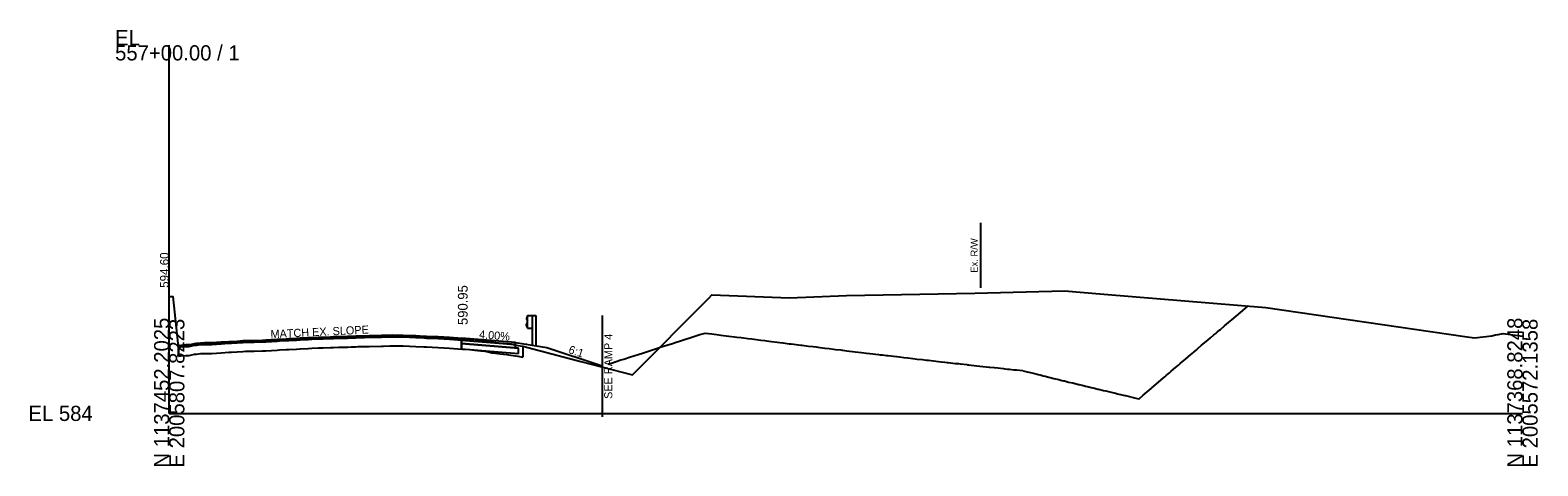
# Model space of a CAD drawing. Extents: x -201 to 2007062, y -213 to 1139737.
# Drawn here: x -25.7 to 252.8, y 9490.3 to 9570.8 of the extents above; entities that cross this region are included whole.
import ezdxf

# ---------------------------------------------------------------- set-up
doc = ezdxf.new("R2010")
doc.units = 0
for name, color, linetype in [('Default', 7, 'Continuous'), ('RD_DTM_Design_FG', 7, 'Continuous'), ('RD_GPK_XS_Cell', 7, 'Continuous'), ('RD_Sketch1', 7, 'Continuous'), ('RD_XS_Base', 7, 'Continuous'), ('RD_XS_ExGround', 7, 'Continuous'), ('RD_XS_ExPaveRet', 7, 'Continuous'), ('RD_XS_ExRW', 7, 'Continuous'), ('RD_XS_GR', 7, 'Continuous'), ('RD_XS_PaveOvlay', 7, 'Continuous'), ('RD_XS_PaveShd', 7, 'Continuous'), ('RD_XS_SideStreet', 7, 'Continuous'), ('RD_XS_TieSlope', 7, 'Continuous'), ('RD_XS_TX_Elev_EX', 7, 'Continuous'), ('RD_XS_TX_Elev_PR', 7, 'Continuous'), ('RD_XS_TX_Slope', 7, 'Continuous')]:
    doc.layers.add(name, color=color, linetype=linetype)

msp = doc.modelspace()

# ---------------------------------------------------------------- linework, layer by layer
at = {"layer": 'RD_DTM_Design_FG'}
msp.add_lwpolyline([(81, 9509.09), (81.13, 9509.13), (81.62, 9509.29), (81.7, 9509.31), (83.45, 9509.87), (83.96, 9510.04), (85.01, 9510.37), (86.64, 9510.9), (87.64, 9511.22), (88.57, 9511.52), (89.86, 9511.93), (90.22, 9512.05), (90.23, 9512.05), (90.91, 9512.27), (92.95, 9512.92), (93.84, 9513.2), (94.09, 9513.28), (94.64, 9513.46), (95.21, 9513.64), (96.15, 9513.95), (98.05, 9514.55), (98.99, 9514.85), (100.26, 9514.69), (100.7, 9514.63), (101.14, 9514.58), (101.54, 9514.52), (101.91, 9514.48), (103.39, 9514.29), (104.4, 9514.16), (104.83, 9514.11), (105.66, 9514), (106.08, 9513.95), (106.88, 9513.85), (107.61, 9513.75), (109.28, 9513.54), (110.02, 9513.45), (110.77, 9513.35), (112.79, 9513.1), (113.34, 9513.03), (113.41, 9513.02), (114.52, 9512.88), (114.87, 9512.84), (115.39, 9512.78), (116.67, 9512.62), (116.92, 9512.59), (118.08, 9512.44), (118.98, 9512.33), (119.49, 9512.27), (119.82, 9512.23), (121.11, 9512.07), (121.94, 9511.97), (122.69, 9511.88), (123.08, 9511.83), (124.06, 9511.72), (124.32, 9511.68), (124.47, 9511.67), (125.18, 9511.58), (126.74, 9511.39), (127.9, 9511.25), (128.82, 9511.14), (129.46, 9511.07), (131.02, 9510.88), (131.32, 9510.85), (131.75, 9510.8), (132.49, 9510.71), (132.83, 9510.67), (133.8, 9510.56), (134.39, 9510.49), (134.89, 9510.43), (135.72, 9510.33), (136.47, 9510.25), (137.35, 9510.14), (138.17, 9510.05), (139.15, 9509.94), (139.92, 9509.85), (140.04, 9509.84), (140.28, 9509.81), (142.09, 9509.6), (142.63, 9509.54), (143.29, 9509.47), (143.73, 9509.42), (143.93, 9509.4), (145.21, 9509.25), (145.8, 9509.19), (146.11, 9509.15), (147.39, 9509.01), (147.48, 9509), (147.5, 9509), (147.73, 9508.97), (148.14, 9508.93), (148.18, 9508.92), (149.78, 9508.75), (151.5, 9508.56), (151.6, 9508.55), (152.4, 9508.46), (152.45, 9508.46), (153.05, 9508.39), (154.15, 9508.28), (154.34, 9508.26), (154.88, 9508.2), (155.22, 9508.16), (156.05, 9508.07), (156.52, 9508.02), (157.72, 9507.9), (157.76, 9507.89), (158.47, 9507.71), (159.14, 9507.54), (160.08, 9507.31), (160.36, 9507.23), (160.5, 9507.2), (160.92, 9507.1), (161.46, 9506.96), (161.82, 9506.87), (163.43, 9506.47), (164.35, 9506.24), (164.93, 9506.1), (165.21, 9506.03), (165.37, 9505.99), (166.16, 9505.8), (166.91, 9505.62), (167.98, 9505.35), (168.08, 9505.33), (168.67, 9505.19), (169.27, 9505.04), (169.91, 9504.88), (170.34, 9504.78), (170.92, 9504.64), (171.15, 9504.59), (171.57, 9504.48), (171.7, 9504.45), (172.59, 9504.24), (173.02, 9504.14), (173.78, 9503.96), (173.99, 9503.91), (174.8, 9503.72), (175.2, 9503.62), (176.51, 9503.31), (176.56, 9503.3), (176.64, 9503.28), (178.6, 9502.82), (179.15, 9502.7), (179.18, 9502.69), (179.95, 9503.36), (181.4, 9504.6), (181.59, 9504.76), (181.81, 9504.96), (181.9, 9505.03), (183.67, 9506.55), (183.9, 9506.75), (184.19, 9507), (184.79, 9507.52), (185.11, 9507.79), (185.88, 9508.45), (186.17, 9508.69), (186.43, 9508.92), (186.77, 9509.21), (187.42, 9509.76), (187.74, 9510.03), (188.22, 9510.45), (188.76, 9510.9), (188.89, 9511.02), (189.32, 9511.39), (189.7, 9511.71), (190.09, 9512.04), (190.72, 9512.58), (191.25, 9513.03), (191.92, 9513.6), (192.37, 9513.97), (192.39, 9513.99), (193, 9514.51), (193.32, 9514.77), (193.58, 9515), (194.08, 9515.41), (194.2, 9515.53), (194.96, 9516.16), (195.68, 9516.77), (196.29, 9517.28), (197.08, 9517.94), (197.48, 9518.28), (197.6, 9518.39), (197.84, 9518.58), (199.35, 9519.85)], dxfattribs=at)
at = {"layer": 'RD_GPK_XS_Cell'}
for q in [(0, 9568.02), (250, 9500)]:
    msp.add_line((0, 9500), q, dxfattribs=at)
at = {"layer": 'RD_XS_Base'}
for points in [[(64, 9512.76), (54, 9513.56)], [(54, 9513.56), (54, 9512.9)], [(64.5, 9512.06), (54, 9512.9)], [(54, 9512.9), (54, 9511.9)], [(54, 9512.9), (64.5, 9512.06)], [(54, 9511.9), (64.5, 9511.06)], [(64, 9512.1), (64, 9512.76)], [(64.5, 9511.06), (64.5, 9512.06)]]:
    msp.add_lwpolyline(points, dxfattribs=at)
at = {"layer": 'RD_XS_ExGround'}
msp.add_lwpolyline([(0, 9521.2), (0.04, 9521.6), (0.65, 9521.63), (1.6, 9512.92), (1.72, 9512.56), (2.16, 9512.61), (3.09, 9512.7), (3.69, 9512.71), (4.16, 9512.81), (4.68, 9512.92), (5.04, 9512.97), (5.79, 9513.04), (6.5, 9513.07), (6.88, 9513.07), (7.85, 9513.09), (9.6, 9513.21), (10.99, 9513.29), (11.48, 9513.31), (12.56, 9513.36), (13.6, 9513.44), (14.12, 9513.47), (15.72, 9513.5), (17.26, 9513.55), (17.84, 9513.59), (18.9, 9513.64), (19.97, 9513.71), (20.39, 9513.72), (21.6, 9513.79), (22.09, 9513.82), (23.53, 9513.89), (24.21, 9513.94), (25.64, 9514.01), (26.33, 9514.04), (27.59, 9514.09), (28.45, 9514.11), (29.79, 9514.17), (30.36, 9514.19), (31.25, 9514.23), (32.93, 9514.25), (33.59, 9514.28), (34.5, 9514.32), (34.82, 9514.33), (36.06, 9514.36), (36.94, 9514.39), (39.2, 9514.45), (39.59, 9514.45), (40.76, 9514.48), (41.18, 9514.49), (43.24, 9514.46), (45.58, 9514.37), (47.03, 9514.3), (47.54, 9514.27), (48.6, 9514.23), (49.67, 9514.18), (51.79, 9514.06), (53.3, 9513.94), (54.19, 9513.88), (55.56, 9513.78), (56.43, 9513.7), (57.58, 9513.59), (58.28, 9513.49), (59.17, 9513.31), (59.57, 9513.22), (60.27, 9513.1), (61.14, 9513), (62.39, 9512.88), (62.7, 9512.84), (63.57, 9512.7), (64.43, 9512.57), (65.34, 9512.4), (76.05, 9509.58), (85.58, 9507.1), (99.72, 9521.36), (100.27, 9521.91), (114.57, 9521.38), (125.11, 9521.77), (148.84, 9522.19), (165.42, 9522.67), (172.63, 9522.06), (202.57, 9519.59), (239.36, 9514.21), (241.13, 9513.95), (244.33, 9514.36), (245.02, 9514.49), (245.53, 9514.59), (246.45, 9514.77), (249.13, 9514.38), (250, 9514.25)], dxfattribs=at)
at = {"layer": 'RD_XS_ExPaveRet'}
for p, q in [((1.72, 9510.56), (1.72, 9512.56)), ((1.72, 9512.23), (1.72, 9510.56)), ((22.09, 9511.82), (23.53, 9511.89)), ((22.09, 9511.82), (23.53, 9511.89)), ((23.53, 9511.89), (24.21, 9511.94)), ((23.53, 9511.89), (24.21, 9511.94)), ((24.21, 9511.94), (25.64, 9512.01)), ((24.21, 9511.94), (25.64, 9512.01)), ((25.64, 9512.01), (26.33, 9512.04)), ((25.64, 9512.01), (26.33, 9512.04)), ((26.33, 9512.04), (27.59, 9512.09)), ((26.33, 9512.04), (27.59, 9512.09)), ((27.59, 9512.09), (28.45, 9512.11)), ((27.59, 9512.09), (28.45, 9512.11)), ((28.45, 9512.11), (29.79, 9512.17)), ((28.45, 9512.11), (29.79, 9512.17)), ((29.79, 9512.17), (30.36, 9512.19)), ((29.79, 9512.17), (30.36, 9512.19)), ((30.36, 9512.19), (31.25, 9512.23)), ((30.36, 9512.19), (31.25, 9512.23)), ((31.25, 9512.23), (32.93, 9512.25)), ((31.25, 9512.23), (32.93, 9512.25)), ((32.93, 9512.25), (33.59, 9512.28)), ((32.93, 9512.25), (33.59, 9512.28)), ((33.59, 9512.28), (34.5, 9512.32)), ((33.59, 9512.28), (34.5, 9512.32)), ((34.5, 9512.32), (34.82, 9512.33)), ((34.5, 9512.32), (34.82, 9512.33)), ((34.82, 9512.33), (36.06, 9512.36)), ((34.82, 9512.33), (36.06, 9512.36)), ((36.06, 9512.36), (36.94, 9512.39)), ((36.06, 9512.36), (36.94, 9512.39)), ((36.94, 9512.39), (39.2, 9512.45)), ((36.94, 9512.39), (39.2, 9512.45)), ((39.2, 9512.45), (39.59, 9512.45)), ((39.2, 9512.45), (39.59, 9512.45)), ((39.59, 9512.45), (40.76, 9512.48)), ((39.59, 9512.45), (40.76, 9512.48)), ((40.76, 9512.48), (41.18, 9512.49)), ((40.76, 9512.48), (41.18, 9512.49)), ((41.18, 9512.49), (43.24, 9512.46)), ((41.18, 9512.49), (43.24, 9512.46)), ((43.24, 9512.46), (45.58, 9512.37)), ((43.24, 9512.46), (45.58, 9512.37)), ((45.58, 9512.37), (47.03, 9512.3)), ((45.58, 9512.37), (47.03, 9512.3)), ((47.03, 9512.3), (47.54, 9512.27)), ((47.03, 9512.3), (47.54, 9512.27)), ((47.54, 9512.27), (48.6, 9512.23)), ((47.54, 9512.27), (48.6, 9512.23)), ((48.6, 9512.23), (49.67, 9512.18)), ((48.6, 9512.23), (49.67, 9512.18)), ((49.67, 9512.18), (51.79, 9512.06)), ((49.67, 9512.18), (51.79, 9512.06)), ((51.79, 9512.06), (53.3, 9511.94)), ((51.79, 9512.06), (53.3, 9511.94)), ((53.3, 9511.94), (54.19, 9511.88)), ((53.3, 9511.94), (54, 9511.89)), ((54, 9512.9), (54, 9513.56)), ((54, 9511.9), (54, 9512.9)), ((54, 9511.9), (54, 9511.89)), ((54, 9511.89), (54, 9511.9)), ((65.34, 9512.4), (65.34, 9510.4)), ((1.72, 9510.56), (2.16, 9510.61)), ((1.72, 9510.56), (2.16, 9510.61)), ((2.16, 9510.61), (3.09, 9510.7)), ((2.16, 9510.61), (3.09, 9510.7)), ((3.09, 9510.7), (3.69, 9510.71)), ((3.09, 9510.7), (3.69, 9510.71)), ((3.69, 9510.71), (4.16, 9510.81)), ((3.69, 9510.71), (4.16, 9510.81)), ((4.16, 9510.81), (4.68, 9510.92)), ((4.16, 9510.81), (4.68, 9510.92)), ((4.68, 9510.92), (5.04, 9510.97)), ((4.68, 9510.92), (5.04, 9510.97)), ((5.04, 9510.97), (5.79, 9511.04)), ((5.04, 9510.97), (5.79, 9511.04)), ((5.79, 9511.04), (6.5, 9511.07)), ((5.79, 9511.04), (6.5, 9511.07)), ((6.5, 9511.07), (6.88, 9511.07)), ((6.5, 9511.07), (6.88, 9511.07)), ((6.88, 9511.07), (7.85, 9511.09)), ((6.88, 9511.07), (7.85, 9511.09)), ((7.85, 9511.09), (9.6, 9511.21)), ((7.85, 9511.09), (9.6, 9511.21)), ((9.6, 9511.21), (10.99, 9511.29)), ((9.6, 9511.21), (10.99, 9511.29)), ((10.99, 9511.29), (11.48, 9511.31)), ((10.99, 9511.29), (11.48, 9511.31)), ((11.48, 9511.31), (12.56, 9511.36)), ((11.48, 9511.31), (12.56, 9511.36)), ((12.56, 9511.36), (13.6, 9511.44)), ((12.56, 9511.36), (13.6, 9511.44)), ((13.6, 9511.44), (14.12, 9511.47)), ((13.6, 9511.44), (14.12, 9511.47)), ((14.12, 9511.47), (15.72, 9511.5)), ((14.12, 9511.47), (15.72, 9511.5)), ((15.72, 9511.5), (17.26, 9511.55)), ((15.72, 9511.5), (17.26, 9511.55)), ((17.26, 9511.55), (17.84, 9511.59)), ((17.26, 9511.55), (17.84, 9511.59)), ((17.84, 9511.59), (18.9, 9511.64)), ((17.84, 9511.59), (18.9, 9511.64)), ((18.9, 9511.64), (19.97, 9511.71)), ((18.9, 9511.64), (19.97, 9511.71)), ((19.97, 9511.71), (20.39, 9511.72)), ((19.97, 9511.71), (20.39, 9511.72)), ((20.39, 9511.72), (21.6, 9511.79)), ((20.39, 9511.72), (21.6, 9511.79)), ((21.6, 9511.79), (22.09, 9511.82)), ((21.6, 9511.79), (22.09, 9511.82)), ((54.19, 9511.88), (55.56, 9511.78)), ((55.56, 9511.78), (56.43, 9511.7)), ((56.43, 9511.7), (57.58, 9511.59)), ((57.58, 9511.59), (58.28, 9511.49)), ((58.28, 9511.49), (59.17, 9511.31)), ((59.17, 9511.31), (59.57, 9511.22)), ((59.57, 9511.22), (60.27, 9511.1)), ((60.27, 9511.1), (61.14, 9511)), ((61.14, 9511), (62.39, 9510.88)), ((62.39, 9510.88), (62.7, 9510.84)), ((62.7, 9510.84), (63.57, 9510.7)), ((63.57, 9510.7), (64.43, 9510.57)), ((64.43, 9510.57), (65.34, 9510.4))]:
    msp.add_line(p, q, dxfattribs=at)
for points in [[(54, 9513.56), (53.3, 9513.61), (51.79, 9513.72), (49.67, 9513.85), (48.6, 9513.9), (47.54, 9513.93), (47.03, 9513.96), (45.58, 9514.04), (43.24, 9514.13), (41.18, 9514.16), (40.76, 9514.15), (39.59, 9514.12), (39.2, 9514.11), (36.94, 9514.06), (36.06, 9514.03), (34.82, 9514), (34.5, 9513.99), (33.59, 9513.95), (32.93, 9513.92), (31.25, 9513.9), (30.36, 9513.86), (29.79, 9513.84), (28.45, 9513.78), (27.59, 9513.75), (26.33, 9513.71), (25.64, 9513.67), (24.21, 9513.61), (23.53, 9513.56), (22.09, 9513.49), (21.6, 9513.46), (20.39, 9513.39), (19.97, 9513.37), (18.9, 9513.31), (17.84, 9513.25), (17.26, 9513.22), (15.72, 9513.17), (14.12, 9513.14), (13.6, 9513.11), (12.56, 9513.03), (11.48, 9512.97), (10.99, 9512.95), (9.6, 9512.88), (7.85, 9512.76), (6.88, 9512.74), (6.5, 9512.74), (5.79, 9512.7), (5.04, 9512.63), (4.68, 9512.58), (4.16, 9512.47), (3.69, 9512.37), (3.09, 9512.37), (2.16, 9512.28), (1.72, 9512.23)], [(1.72, 9512.23), (1.72, 9512.23)]]:
    msp.add_lwpolyline(points, dxfattribs=at)
at = {"layer": 'RD_XS_ExRW'}
msp.add_line((149.85, 9535.22), (149.85, 9523.22), dxfattribs=at)
at = {"layer": 'RD_XS_GR'}
for p, q in [((66.17, 9517.94), (66, 9517.54)), ((66, 9517.54), (66, 9517.44)), ((66.17, 9515.75), (66.17, 9518.09)), ((66.17, 9518.09), (67.08, 9518.09)), ((67.08, 9518.09), (67.08, 9512.59)), ((67.08, 9518.09), (67.75, 9518.09)), ((67.75, 9518.09), (67.75, 9512.48)), ((66, 9517.44), (66.17, 9517.04)), ((66, 9516.4), (66.17, 9516.8)), ((66, 9516.3), (66, 9516.4)), ((66.17, 9515.9), (66, 9516.3)), ((66.17, 9515.75), (67.08, 9515.75))]:
    msp.add_line(p, q, dxfattribs=at)
for centre, major_axis in [((66, 9512.77), (0, -0.02)), ((69.75, 9512.17), (0, -0.0204))]:
    msp.add_ellipse(centre, major_axis=major_axis, ratio=0.5, dxfattribs=at)
at = {"layer": 'RD_XS_PaveOvlay'}
for points in [[(1.72, 9512.56), (2.16, 9512.61), (3.09, 9512.7), (3.69, 9512.71), (4.16, 9512.81), (4.68, 9512.92), (5.04, 9512.97), (5.79, 9513.04), (6.5, 9513.07), (6.88, 9513.07), (7.85, 9513.09), (9.6, 9513.21), (10.99, 9513.29), (11.48, 9513.31), (12.56, 9513.36), (13.6, 9513.44), (14.12, 9513.47), (15.72, 9513.5), (17.26, 9513.55), (17.84, 9513.59), (18.9, 9513.64), (19.97, 9513.71), (20.39, 9513.72), (21.6, 9513.79), (22.09, 9513.82), (23.53, 9513.89), (24.21, 9513.94), (25.64, 9514.01), (26.33, 9514.04), (27.59, 9514.09), (28.45, 9514.11), (29.79, 9514.17), (30.36, 9514.19), (31.25, 9514.23), (32.93, 9514.25), (33.59, 9514.28), (34.5, 9514.32), (34.82, 9514.33), (36.06, 9514.36), (36.94, 9514.39), (39.2, 9514.45), (39.59, 9514.45), (40.76, 9514.48), (41.18, 9514.49), (43.24, 9514.46), (45.58, 9514.37), (47.03, 9514.3), (47.54, 9514.27), (48.6, 9514.23), (49.67, 9514.18), (51.79, 9514.06), (53.3, 9513.94), (54, 9513.89)], [(1.72, 9512.23), (2.16, 9512.28), (3.09, 9512.37), (3.69, 9512.37), (4.16, 9512.47), (4.68, 9512.58), (5.04, 9512.63), (5.79, 9512.7), (6.5, 9512.74), (6.88, 9512.74), (7.85, 9512.76), (9.6, 9512.88), (10.99, 9512.95), (11.48, 9512.97), (12.56, 9513.03), (13.6, 9513.11), (14.12, 9513.14), (15.72, 9513.17), (17.26, 9513.22), (17.84, 9513.25), (18.9, 9513.31), (19.97, 9513.37), (20.39, 9513.39), (21.6, 9513.46), (22.09, 9513.49), (23.53, 9513.56), (24.21, 9513.61), (25.64, 9513.67), (26.33, 9513.71), (27.59, 9513.75), (28.45, 9513.78), (29.79, 9513.84), (30.36, 9513.86), (31.25, 9513.9), (32.93, 9513.92), (33.59, 9513.95), (34.5, 9513.99), (34.82, 9514), (36.06, 9514.03), (36.94, 9514.06), (39.2, 9514.11), (39.59, 9514.12), (40.76, 9514.15), (41.18, 9514.16), (43.24, 9514.13), (45.58, 9514.04), (47.03, 9513.96), (47.54, 9513.93), (48.6, 9513.9), (49.67, 9513.85), (51.79, 9513.72), (53.3, 9513.61), (54, 9513.56)]]:
    msp.add_lwpolyline(points, dxfattribs=at)
at = {"layer": 'RD_XS_PaveShd'}
for points in [[(64, 9513.09), (54, 9513.89)], [(54, 9513.89), (54, 9513.56)], [(54, 9513.56), (64, 9512.76)], [(64, 9512.76), (64, 9513.09)]]:
    msp.add_lwpolyline(points, dxfattribs=at)
at = {"layer": 'RD_XS_SideStreet'}
msp.add_line((79.99, 9518.06), (79.99, 9499.38), dxfattribs=at)
at = {"layer": 'RD_XS_TieSlope'}
msp.add_line((64, 9513.09), (69.75, 9512.17), dxfattribs=at)
msp.add_lwpolyline([(69.75, 9512.17), (79.99, 9508.76)], dxfattribs=at)

# ---------------------------------------------------------------- texts
at = {"layer": 'Default'}
msp.add_text('-', height=0.0001, dxfattribs=at).set_placement((0, 9500))
at = {"layer": 'RD_GPK_XS_Cell'}
for s, p in [('EL', (-10, 9568.02)), ('557+00.00 / 1', (-10, 9565.22)), ('EL 584', (-26, 9498.6))]:
    msp.add_text(s, height=2.8, dxfattribs=at).set_placement(p)
for s, p in [('N 1137452.2025', (0, 9490)), ('N 1137368.8248', (250, 9490)), ('E 2005807.8223', (2.8, 9490)), ('E 2005572.1358', (252.8, 9490))]:
    msp.add_text(s, height=2.8, rotation=90, dxfattribs=at).set_placement(p)
at = {"layer": 'RD_Sketch1'}
for s, p in [('Exterior Boundary', (110.19, 9521.47)), ('LOC_C_R', (110.42, 9521.47)), ('Exterior Boundary', (53.44, 9513.84)), ('EP_X_R', (53.73, 9513.84)), ('EP_X2', (53.79, 9512.85)), ('EP_X3', (53.79, 9511.85)), ('EP_X1', (53.8, 9513.51)), ('ES1_R', (63.78, 9512.71)), ('ES2_R', (63.78, 9512.05)), ('ES_R', (63.82, 9513.04)), ('Shoulder_R', (69.13, 9512.16)), ('ES3_R', (63.78, 9511.05))]:
    msp.add_text(s, height=0.05, dxfattribs=at).set_placement(p)
at = {"layer": 'RD_XS_ExRW'}
msp.add_text('Ex. R/W ', height=1.3, rotation=90, dxfattribs=at).set_placement((149.35, 9525.99))
at = {"layer": 'RD_XS_SideStreet'}
msp.add_text('SEE RAMP 4', height=1.5, rotation=90, dxfattribs=at).set_placement((81.86, 9502.68))
at = {"layer": 'RD_XS_TX_Elev_EX'}
msp.add_text('594.60', height=1.6, rotation=90, dxfattribs=at).set_placement((-0.1, 9523.2))
at = {"layer": 'RD_XS_TX_Elev_PR'}
msp.add_text('590.95', height=1.8, rotation=90, dxfattribs=at).set_placement((55.13, 9516.33))
at = {"layer": 'RD_XS_TX_Slope'}
for s, rotation, p in [('MATCH EX. SLOPE', 2.7318, (18.75, 9513.89)), ('4.00%', 355.4261, (57.2, 9513.89)), ('6:1', 341.5651, (73.64, 9511.17))]:
    msp.add_text(s, height=1.5, rotation=rotation, dxfattribs=at).set_placement(p)

doc.saveas('drawing.dxf')
